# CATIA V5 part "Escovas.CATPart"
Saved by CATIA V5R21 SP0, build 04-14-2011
Part number: Escovas
Definition: Escovas
Nomenclature: Escovas
Source: Unknown
Bounding box of the stored display mesh (mm): x -3.218 to 3.218, y -0.01 to 2.01, z -3.663 to 3.663
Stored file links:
  C:\Users\beatr\OneDrive\Documents\UNB\2026_1\Pi1\Componentes eletronicos\Escovas.CATPart
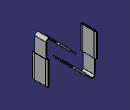
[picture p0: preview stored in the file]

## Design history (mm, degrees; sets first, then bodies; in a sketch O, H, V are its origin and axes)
Body1 "Sólido1" (main body)
  Solid1: solid without history
Body2 "Sólido1"
  Solid2: solid without history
